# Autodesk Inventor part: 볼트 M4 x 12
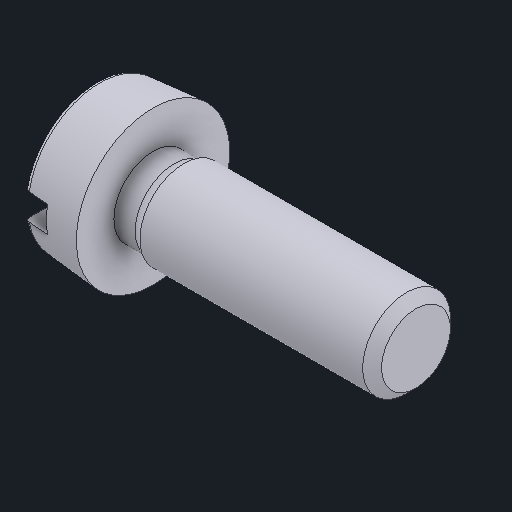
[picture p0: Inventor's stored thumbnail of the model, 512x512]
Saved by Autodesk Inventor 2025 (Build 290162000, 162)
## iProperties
Created: 2025-08
Part Number: 볼트 M4 x 12
Material: 강철, 연강
Description: 6각머리 태핑 나사
Document SubType Name: Modeling
Designer: infra012
Density: 7.85 g/cm^3
Appearance: 기본값
Author: jhkim
Sending System: Autodesk Inventor 2026
Preprocessor: ST-DEVELOPER v20.1
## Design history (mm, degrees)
sketch "스케치1"
  geometry: 1 further point
  constraints: 1 other
feature "Solid1"
node "솔리드1"
